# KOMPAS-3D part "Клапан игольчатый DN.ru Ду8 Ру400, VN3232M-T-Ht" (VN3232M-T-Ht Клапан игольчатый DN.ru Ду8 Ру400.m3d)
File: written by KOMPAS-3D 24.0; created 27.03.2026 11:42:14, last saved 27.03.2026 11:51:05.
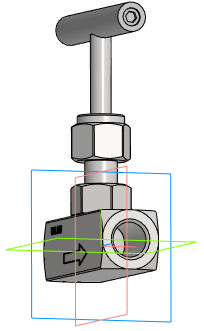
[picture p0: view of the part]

Document properties: Автор: Илья; Полное имя файла: VN3232M-T-Ht Клапан игольчатый DN.ru Ду8 Ру400.cdw

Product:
- Body: Body3  | qty 1
    Масса: 0.248386
- Part/product: Клапан игольчатый DN.ru Ду8 Ру400  | designation VN3232M-T-Ht
    Масса: 0.35
    Раздел спецификации: Прочие изделия
    Форматы листов документа: A4
    Примечание: D090-02129

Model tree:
1. Body3  (labels: Body3)

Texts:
  VN3232M-T-Ht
